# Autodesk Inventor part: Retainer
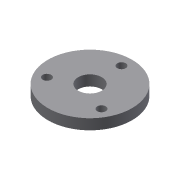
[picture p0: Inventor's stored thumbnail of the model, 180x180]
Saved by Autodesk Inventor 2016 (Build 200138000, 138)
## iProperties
Created: 2009-04
Part Number: Retainer
Document SubType Name: Modeling
Designer: Sham
Density: 1 g/cm^3
Material: Generic
Appearance: Default
Author: Sham
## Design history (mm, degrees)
sketch "Sketch1"
  geometry: C1 r 100 at (0, 0); C2 r 28 at (0, 0)
  constraints: 2 centre point, 1 coincident
  dimensions: "d0" = 200 diameter of C1; "d1" = 56 diameter of C2
extrude "Extrusion2" new body sketch "Sketch1" distance "d10" = 25; taper "d11" = 0 deg
sketch "Sketch2"
  geometry: C1 r 28 at (0, 0) reference; 1 further point
  constraints: 1 vertical alignment
  dimensions: "d12" = 75 distance of C1.centre point (0, 75)
hole "Hole1" sketch "Sketch2" at (0, 75) diameter "d13" = 20.3; stored, may be unused: countersink angle "d17" = 90 deg, drill point angle "d19" = 118 deg; dims "d14" = 6, "d15" = 4, "d16" = 2, "d18" = 8
pattern_circular "Circular Pattern1" dims angle "d21" = 360 deg
body "Solid2"
